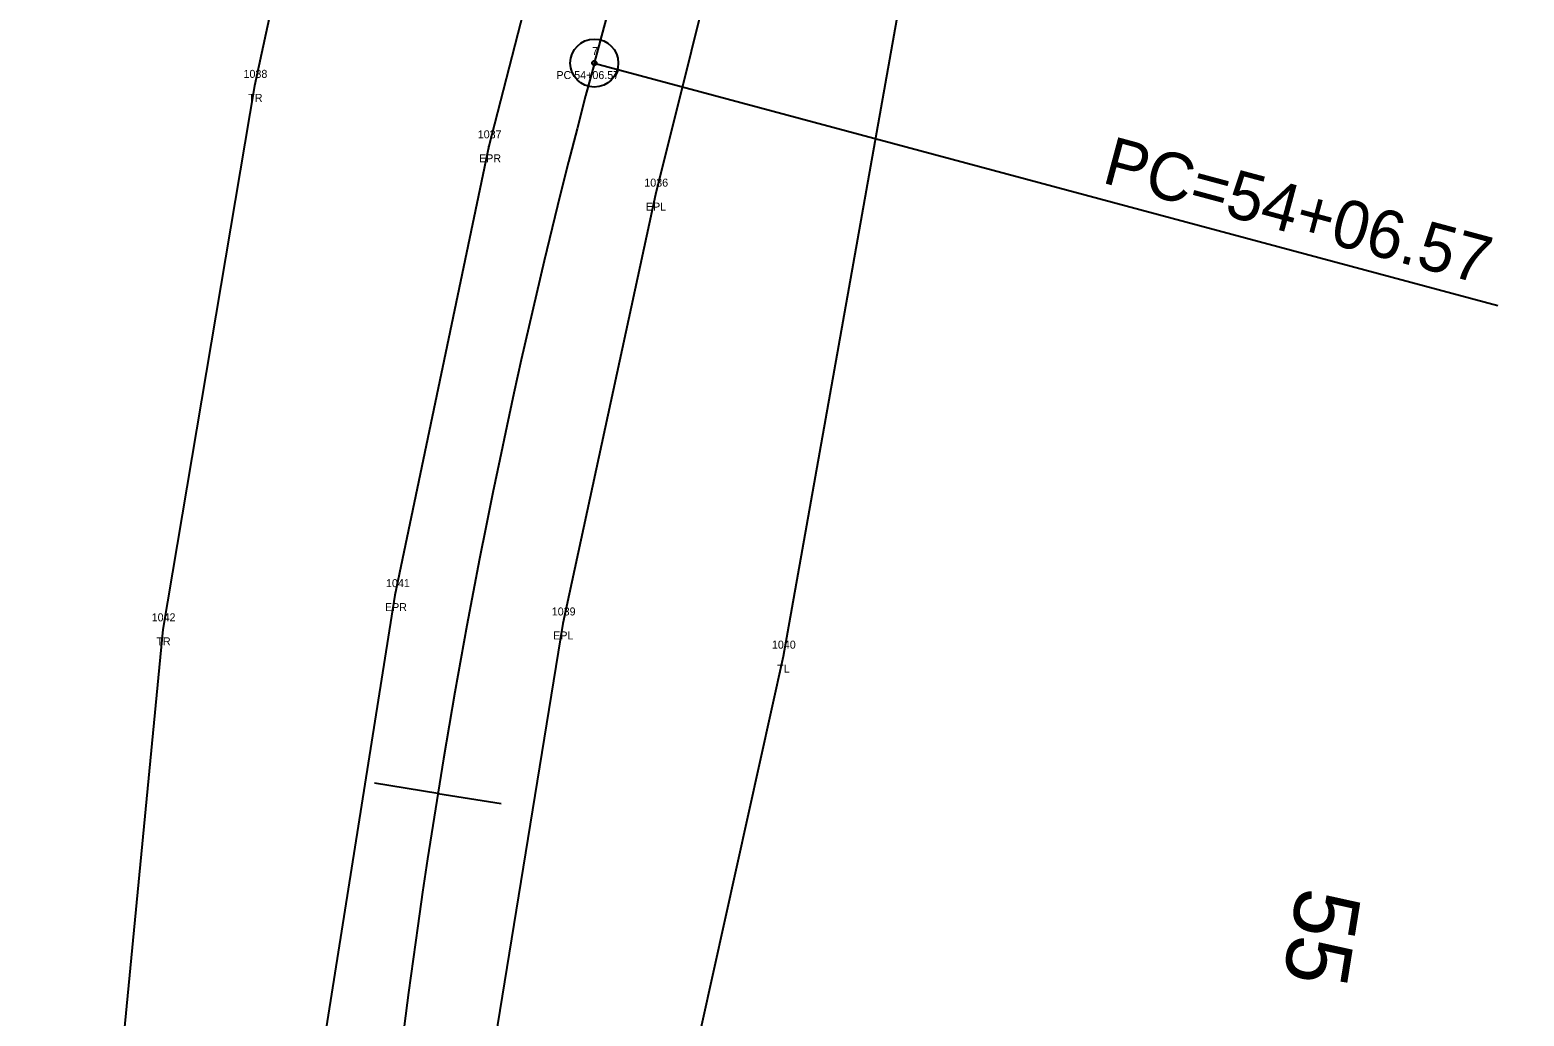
# Model space of a CAD drawing. Extents: x 2432632 to 2433497, y 684847 to 688233.
# Drawn here: x 2432885.8 to 2433072.6, y 687281.7 to 687405 of the extents above; entities that cross this region are included whole.
import ezdxf

# ---------------------------------------------------------------- set-up
doc = ezdxf.new("R2010")
doc.units = 0
for name, color, linetype in [('RD_EX_Road', 7, 'Continuous'), ('RD_EX_Road_txCode', 7, 'Continuous'), ('RD_EX_VEG', 7, 'Continuous'), ('RD_EX_VEG_txCode', 7, 'Continuous'), ('RD_HC_Cl', 7, 'Continuous'), ('RD_HC_Data', 7, 'Continuous'), ('RD_HC_Data_Tic', 7, 'Continuous'), ('RD_HC_TX_Sta50', 7, 'Continuous'), ('RD_HC_txCode', 7, 'Continuous'), ('RD_SMD_Locator', 7, 'Continuous')]:
    doc.layers.add(name, color=color, linetype=linetype)

msp = doc.modelspace()

# ---------------------------------------------------------------- linework, layer by layer
at = {"layer": 'RD_EX_Road'}
for points in [[(2433130.63, 688090.22), (2433103.18, 687988.73), (2433075.68, 687887.89), (2433049.83, 687790.75), (2433022.33, 687689.17), (2432994.76, 687586.82), (2432966.23, 687480.17), (2432943.15, 687390.42), (2432931.4, 687334.3), (2432921.83, 687273.88), (2432915.64, 687215.4), (2432913.86, 687159.12), (2432915.08, 687107.55), (2432919.97, 687053.4), (2432928.7, 686998.89), (2432946.77, 686924.59), (2432964.57, 686864), (2432997.3, 686766.34), (2433031.44, 686666.38), (2433066.06, 686565.78), (2433098.73, 686469.74)], [(2432986.34, 687474.01), (2432964, 687384.38), (2432952.4, 687330.76), (2432943.09, 687273.42), (2432937.12, 687213.43), (2432935.51, 687158.7), (2432936.54, 687110.38), (2432944.97, 687033.04), (2432950.24, 687002.26), (2432966.49, 686930.23), (2432984.9, 686870.1)]]:
    msp.add_lwpolyline(points, dxfattribs=at)
at = {"layer": 'RD_EX_VEG'}
for points in [[(2433112.43, 688094.61), (2433041.17, 687898.89), (2432988.9, 687699.78), (2432947.96, 687578.08), (2432935.9, 687556.87), (2432944.3, 687538.7), (2432913.88, 687397.98), (2432902.4, 687330.02), (2432885.78, 687157.56), (2432894.43, 687032.93), (2432918.07, 686924.4), (2432974.73, 686759.54), (2433073.82, 686456.42), (2433099.9, 686365.23), (2433115.47, 686257.21), (2433114.64, 686158.77), (2433095.68, 686092.78)], [(2433166.25, 688082.87), (2433111.93, 687876.69), (2433067.75, 687703.46), (2433065.05, 687678.03), (2433052.74, 687645.62), (2433005.45, 687469.88), (2432979.96, 687326.61), (2432966.8, 687267.34), (2432959.05, 687210.65), (2432959.25, 687071.62), (2432974.82, 687014.37), (2432998.13, 686938.9), (2433012.99, 686878.7), (2433054.45, 686782.35), (2433123.54, 686586.06), (2433129.82, 686546.35), (2433158.34, 686434.26), (2433192.79, 686274.67), (2433189.42, 686162.6), (2433197.4, 686074.41)]]:
    msp.add_lwpolyline(points, dxfattribs=at)
at = {"layer": 'RD_HC_Cl'}
msp.add_line((2433140.58, 688087.72), (2432956.34, 687400.83), dxfattribs=at)
msp.add_arc((2433840.56, 687163.67), 915.47, 164.98581, 198.81644, dxfattribs=at)
at = {"layer": 'RD_HC_Data'}
msp.add_line((2432956.34, 687400.83), (2433069.28, 687370.53), dxfattribs=at)
for radius in [3, 0.282]:
    msp.add_circle((2432956.34, 687400.83), radius, dxfattribs=at)
at = {"layer": 'RD_HC_Data_Tic'}
for q in [(2432928.88, 687310.78), (2432944.68, 687308.24)]:
    msp.add_line((2432936.78, 687309.51), q, dxfattribs=at)
at = {"layer": 'RD_SMD_Locator'}
for centre in [(2432956.34, 687400.83), (2432913.88, 687397.98), (2432943.15, 687390.42), (2432964, 687384.38), (2432931.4, 687334.3), (2432902.4, 687330.02), (2432952.4, 687330.76), (2432979.96, 687326.61)]:
    msp.add_circle(centre, 0.001, dxfattribs=at)

# ---------------------------------------------------------------- texts
at = {"layer": 'RD_EX_Road_txCode'}
for s, p in [('1037', (2432941.77, 687391.42)), ('EPR', (2432941.93, 687388.42)), ('1036', (2432962.59, 687385.38)), ('EPL', (2432962.79, 687382.38)), ('1041', (2432930.3, 687335.3)), ('EPR', (2432930.17, 687332.3)), ('1039', (2432951.02, 687331.76)), ('EPL', (2432951.2, 687328.76))]:
    msp.add_text(s, height=1, dxfattribs=at).set_placement(p)
at = {"layer": 'RD_EX_VEG_txCode'}
for s, p in [('1038', (2432912.49, 687398.98)), ('TR', (2432913.08, 687395.98)), ('1042', (2432901.01, 687331.02)), ('TR', (2432901.6, 687328.02)), ('1040', (2432978.54, 687327.61)), ('TL', (2432979.19, 687324.61))]:
    msp.add_text(s, height=1, dxfattribs=at).set_placement(p)
at = {"layer": 'RD_HC_Data'}
msp.add_text('PC=54+06.57', height=6, rotation=344.9858, dxfattribs=at).set_placement((2433019.64, 687385.92))
at = {"layer": 'RD_HC_TX_Sta50'}
msp.add_text('55', height=8, rotation=260.8331, dxfattribs=at).set_placement((2433044.32, 687297.99))
at = {"layer": 'RD_HC_txCode'}
for s, p in [('7', (2432956.06, 687401.83)), ('PC 54+06.57', (2432951.6, 687398.83))]:
    msp.add_text(s, height=1, dxfattribs=at).set_placement(p)

doc.saveas('drawing.dxf')
